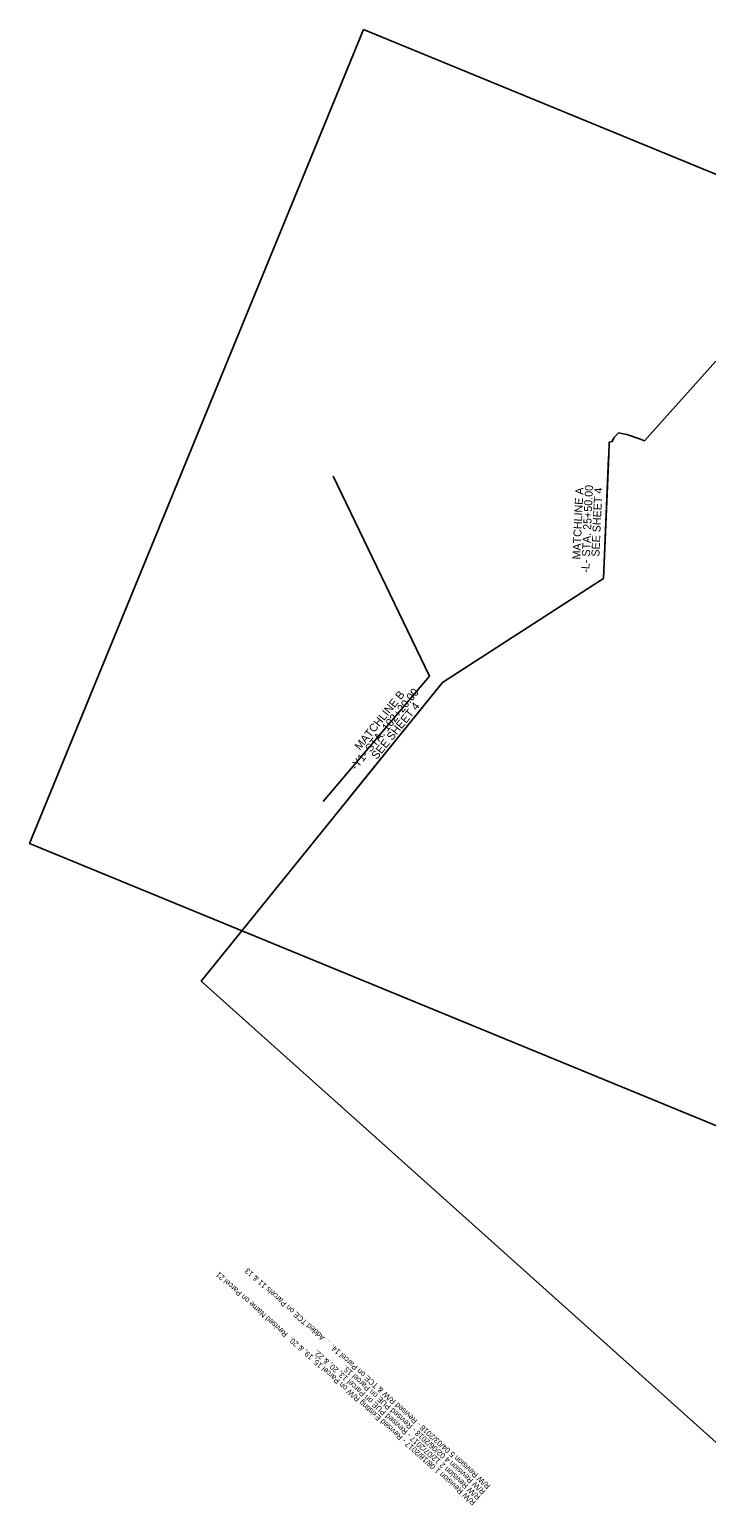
# Model space of a CAD drawing. Extents: x 2090929 to 2092987, y 862751 to 864596.
# Drawn here: x 2090929 to 2091776, y 862751 to 864596 of the extents above; entities that cross this region are included whole.
import ezdxf

# ---------------------------------------------------------------- set-up
doc = ezdxf.new("R2010")
doc.units = 0
for name, color, linetype in [('Matchline', 7, 'Continuous'), ('Matchline Text', 7, 'Continuous'), ('Prop DSN Text', 7, 'Continuous'), ('Scratch_Level_6', 7, 'Continuous'), ('Sheet Clip Boundary CELL', 7, 'Continuous')]:
    doc.layers.add(name, color=color, linetype=linetype)

msp = doc.modelspace()

# ---------------------------------------------------------------- linework, layer by layer
at = {"layer": 'Matchline'}
for p, q in [((2091646.7, 863909.8), (2091653.5, 864064)), ((2091328.8, 863635.3), (2091445.4, 863779.5))]:
    msp.add_line(p, q, dxfattribs=at)
at = {"layer": 'Scratch_Level_6'}
for p, q in [((2091309, 864037.4), (2091429.5, 863787.6)), ((2091429.5, 863787.6), (2091296.4, 863630.9))]:
    msp.add_line(p, q, dxfattribs=at)
msp.add_lwpolyline([(2091346.9, 864595.8), (2092919.5, 863950), (2092501.6, 862932.5), (2090929.1, 863578.3)], close=True, dxfattribs=at)
at = {"layer": 'Sheet Clip Boundary CELL'}
msp.add_lwpolyline([(2091803.8, 862815.7), (2091354.2, 863218.1), (2091143.8, 863406.4), (2091143.8, 863406.4), (2091143.8, 863406.4), (2091445.4, 863779.5), (2091646.7, 863909.8), (2091653.3, 864060.7), (2091653.5, 864064), (2091654.2, 864080.1), (2091657.8, 864080.8), (2091659.8, 864085.3), (2091665.5, 864091.7), (2091676, 864089.7), (2091692.1, 864084.4), (2091698.1, 864081.6), (2091698.1, 864081.6), (2091698.1, 864081.6), (2091787.3, 864181.2)], dxfattribs=at)

# ---------------------------------------------------------------- texts
at = {"layer": 'Matchline Text'}
for s, rotation, p in [('-L- STA. 25+50.00', 87.4725, (2091629, 863916.8)), ('MATCHLINE A', 87.4725, (2091617.9, 863933.3)), ('SEE SHEET 4', 87.4725, (2091641.7, 863936.8)), ('-Y1- STA. 102+20.00 ', 51.0406, (2091337.4, 863669.3)), ('MATCHLINE B', 51.0406, (2091342.4, 863694.3)), ('SEE SHEET 4', 51.0406, (2091363.4, 863682.8))]:
    msp.add_text(s, height=10, rotation=rotation, dxfattribs=at).set_placement(p)
at = {"layer": 'Prop DSN Text'}
for s, p in [('R/W Revision 5 04/03/2018 - Revised R/W & TCE on Parcel 14.  .  Added TCE on Parcels 11 & 13', (2091506.1, 862776.2)), ('R/W Revision 1 08/18/2017 - Revised Existing R/W on Parcel 15, 19, & 20.  Revised Name on Parcel 21', (2091487.7, 862755.7)), ('R/W Revision 2 12/07/2017 - Revised PUE on Parcel 13, 20, & 22.', (2091493.8, 862762.5)), ('R/W Revision 4 02/06/2018 - Revised PUE on Parcel 15.', (2091500, 862769.4))]:
    msp.add_text(s, height=7, rotation=138.1715, dxfattribs=at).set_placement(p)

doc.saveas('drawing.dxf')
